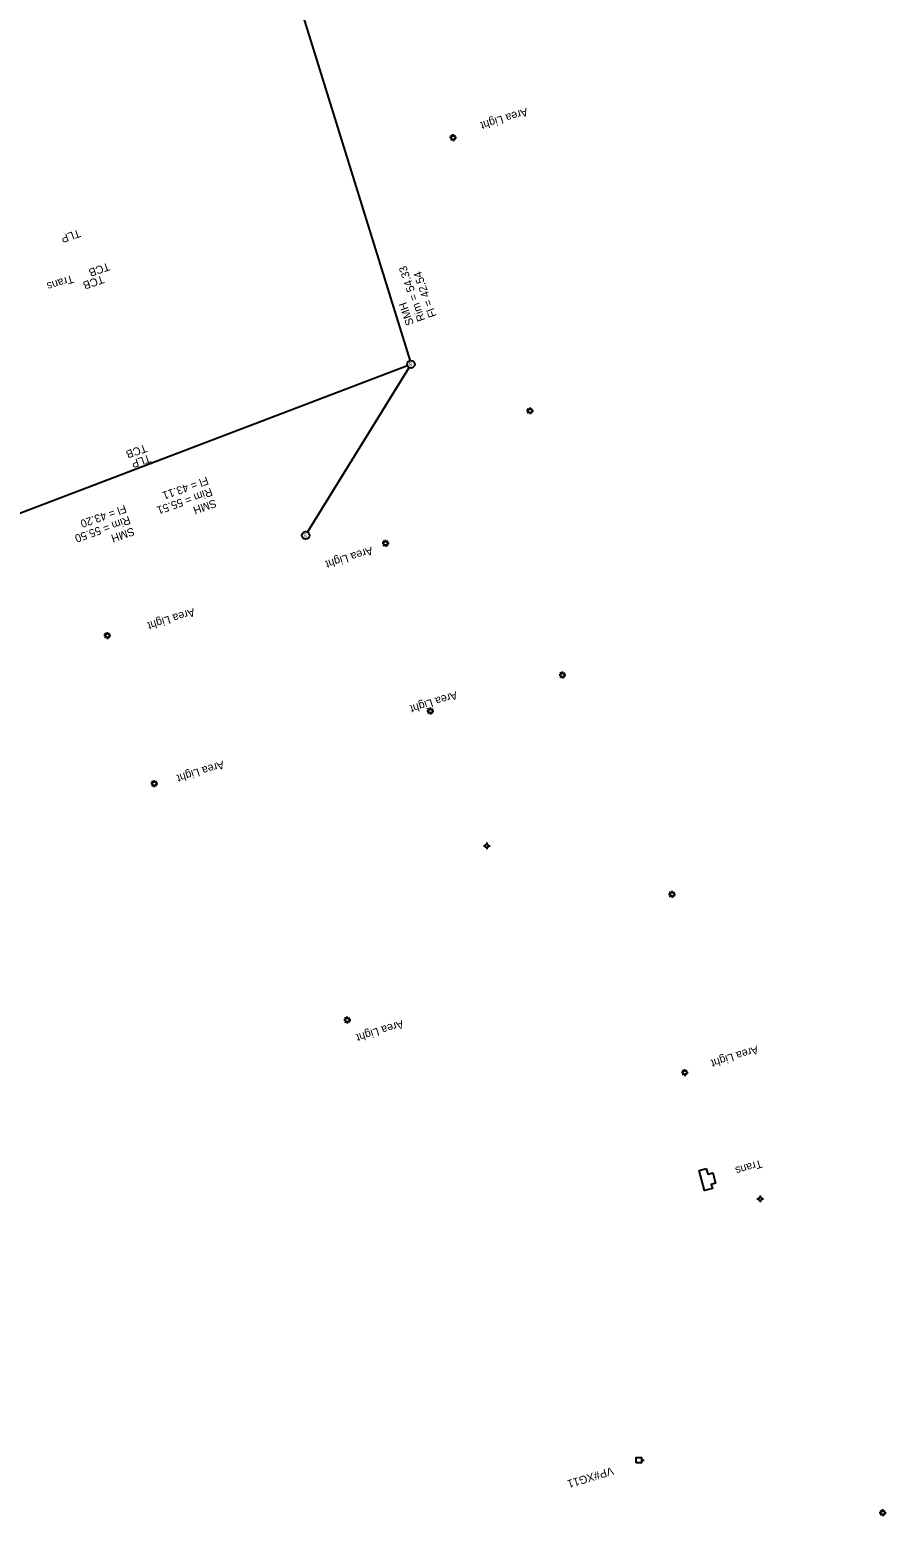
# Model space of a CAD drawing. Extents: x 3872070 to 3879223, y 293944 to 310567.
# Drawn here: x 3875034 to 3875355, y 305445 to 306002 of the extents above; entities that cross this region are included whole.
import ezdxf

# ---------------------------------------------------------------- set-up
doc = ezdxf.new("R2010")
doc.units = 0
for name, color, linetype in [('Level 3', 7, 'Continuous'), ('Level 33', 7, 'Continuous'), ('Level 34', 7, 'Continuous'), ('Level 39', 7, 'Continuous'), ('Level 4', 7, 'Continuous'), ('Level 5', 7, 'Continuous')]:
    doc.layers.add(name, color=color, linetype=linetype)

msp = doc.modelspace()

# ---------------------------------------------------------------- linework, layer by layer
at = {"layer": 'Level 3'}
for p, q in [((3875176.36, 305878.22), (3875111.39, 306087.65)), ((3875174.8, 305876.27), (3875020.61, 305817.48)), ((3875137.72, 305814.13), (3875175.9, 305875.76))]:
    msp.add_line(p, q, dxfattribs=at)
for centre in [(3875176.54, 305876.99), (3875137.08, 305812.87)]:
    msp.add_circle(centre, 1.41, dxfattribs=at)
at = {"layer": 'Level 4'}
for p, q in [((3875191.6, 305961.94), (3875191.03, 305961.94)), ((3875191.81, 305962.45), (3875191.41, 305962.86)), ((3875192.33, 305962.66), (3875192.33, 305963.24)), ((3875192.84, 305962.45), (3875193.25, 305962.86)), ((3875193.05, 305961.94), (3875193.63, 305961.94)), ((3875191.41, 305961.02), (3875191.81, 305961.42)), ((3875192.33, 305961.21), (3875192.33, 305960.64)), ((3875193.25, 305961.02), (3875192.84, 305961.42)), ((3875220.43, 305859.54), (3875219.86, 305859.54)), ((3875220.64, 305860.06), (3875220.24, 305860.46)), ((3875220.24, 305858.62), (3875220.64, 305859.03)), ((3875221.16, 305860.27), (3875221.16, 305860.84)), ((3875221.16, 305858.82), (3875221.16, 305858.24)), ((3875221.67, 305860.06), (3875222.08, 305860.46)), ((3875222.08, 305858.62), (3875221.67, 305859.03)), ((3875221.88, 305859.54), (3875222.46, 305859.54)), ((3875166.28, 305809.89), (3875165.71, 305809.89)), ((3875166.49, 305810.41), (3875166.09, 305810.81)), ((3875166.09, 305808.98), (3875166.49, 305809.38)), ((3875167.01, 305810.62), (3875167.01, 305811.19)), ((3875167.01, 305809.17), (3875167.01, 305808.59)), ((3875167.52, 305810.41), (3875167.93, 305810.81)), ((3875167.93, 305808.98), (3875167.52, 305809.38)), ((3875167.73, 305809.89), (3875168.31, 305809.89)), ((3875062.07, 305775.32), (3875061.5, 305775.32)), ((3875062.29, 305775.84), (3875061.88, 305776.24)), ((3875061.88, 305774.41), (3875062.29, 305774.81)), ((3875062.8, 305776.05), (3875062.8, 305776.62)), ((3875062.8, 305774.6), (3875062.8, 305774.02)), ((3875063.31, 305775.84), (3875063.72, 305776.24)), ((3875063.72, 305774.41), (3875063.31, 305774.81)), ((3875063.52, 305775.32), (3875064.1, 305775.32)), ((3875232.8, 305761.03), (3875232.39, 305761.44)), ((3875233.31, 305761.24), (3875233.31, 305761.82)), ((3875233.82, 305761.03), (3875234.23, 305761.44)), ((3875232.58, 305760.52), (3875232.01, 305760.52)), ((3875232.39, 305759.6), (3875232.8, 305760.01)), ((3875233.31, 305759.79), (3875233.31, 305759.22)), ((3875234.23, 305759.6), (3875233.82, 305760.01)), ((3875234.03, 305760.52), (3875234.61, 305760.52)), ((3875183.1, 305747.03), (3875182.52, 305747.03)), ((3875183.31, 305747.54), (3875182.91, 305747.95)), ((3875182.91, 305746.11), (3875183.31, 305746.52)), ((3875183.83, 305747.75), (3875183.83, 305748.33)), ((3875183.83, 305746.3), (3875183.83, 305745.73)), ((3875184.34, 305747.54), (3875184.74, 305747.95)), ((3875184.74, 305746.11), (3875184.34, 305746.52)), ((3875184.55, 305747.03), (3875185.12, 305747.03)), ((3875079.64, 305719.82), (3875079.06, 305719.82)), ((3875079.85, 305720.34), (3875079.44, 305720.74)), ((3875079.44, 305718.91), (3875079.85, 305719.31)), ((3875080.36, 305720.55), (3875080.36, 305721.12)), ((3875080.36, 305719.1), (3875080.36, 305718.52)), ((3875080.87, 305720.34), (3875081.28, 305720.74)), ((3875081.28, 305718.91), (3875080.87, 305719.31)), ((3875081.09, 305719.82), (3875081.66, 305719.82)), ((3875273.66, 305678.3), (3875273.08, 305678.3)), ((3875273.87, 305678.81), (3875273.46, 305679.22)), ((3875273.46, 305677.38), (3875273.87, 305677.79)), ((3875274.38, 305679.02), (3875274.38, 305679.6)), ((3875274.38, 305677.57), (3875274.38, 305677)), ((3875274.9, 305678.81), (3875275.3, 305679.22)), ((3875275.3, 305677.38), (3875274.9, 305677.79)), ((3875275.11, 305678.3), (3875275.68, 305678.3)), ((3875151.95, 305631.25), (3875151.38, 305631.25)), ((3875152.16, 305631.76), (3875151.76, 305632.17)), ((3875151.76, 305630.33), (3875152.16, 305630.74)), ((3875152.68, 305631.97), (3875152.68, 305632.55)), ((3875152.68, 305630.52), (3875152.68, 305629.95)), ((3875153.19, 305631.76), (3875153.6, 305632.17)), ((3875153.6, 305630.33), (3875153.19, 305630.74)), ((3875153.4, 305631.25), (3875153.98, 305631.25)), ((3875278.43, 305611.54), (3875277.85, 305611.54)), ((3875278.64, 305612.05), (3875278.23, 305612.46)), ((3875278.23, 305610.62), (3875278.64, 305611.03)), ((3875279.15, 305612.27), (3875279.15, 305612.84)), ((3875279.15, 305610.82), (3875279.15, 305610.24)), ((3875279.67, 305612.05), (3875280.07, 305612.46)), ((3875280.07, 305610.62), (3875279.67, 305611.03)), ((3875279.88, 305611.54), (3875280.45, 305611.54)), ((3875262.94, 305466.24), (3875263.94, 305466.24)), ((3875352.6, 305446.53), (3875352.03, 305446.53)), ((3875352.81, 305447.04), (3875352.41, 305447.45)), ((3875352.41, 305445.61), (3875352.81, 305446.02)), ((3875353.33, 305447.26), (3875353.33, 305447.83)), ((3875353.33, 305445.8), (3875353.33, 305445.23)), ((3875353.84, 305447.04), (3875354.25, 305447.45)), ((3875354.25, 305445.61), (3875353.84, 305446.02)), ((3875354.05, 305446.53), (3875354.63, 305446.53))]:
    msp.add_line(p, q, dxfattribs=at)
msp.add_lwpolyline([(3875287.2, 305575.53), (3875287.76, 305573.45), (3875289.6, 305573.94), (3875290.64, 305570.03), (3875289.08, 305569.61), (3875289.49, 305568.11), (3875286.52, 305567.32), (3875284.52, 305574.81), (3875287.2, 305575.53)], dxfattribs=at)
msp.add_lwpolyline([(3875260.94, 305465.24), (3875260.94, 305467.24), (3875262.94, 305467.24), (3875262.94, 305465.24)], close=True, dxfattribs=at)
for centre in [(3875192.33, 305961.94), (3875221.16, 305859.54), (3875167.01, 305809.89), (3875062.8, 305775.32), (3875233.31, 305760.52), (3875183.83, 305747.03), (3875080.36, 305719.82), (3875274.38, 305678.3), (3875152.68, 305631.25), (3875279.15, 305611.54), (3875353.33, 305446.53)]:
    msp.add_circle(centre, 0.725, dxfattribs=at)
at = {"layer": 'Level 5'}
for p, q in [((3875203.68, 305696.46), (3875204.3, 305696.46)), ((3875204.93, 305697.71), (3875204.93, 305697.08)), ((3875204.93, 305695.84), (3875204.93, 305695.21)), ((3875205.54, 305696.46), (3875206.18, 305696.46)), ((3875306.19, 305564.16), (3875306.81, 305564.16)), ((3875307.44, 305565.41), (3875307.44, 305564.78)), ((3875307.44, 305563.54), (3875307.44, 305562.91)), ((3875308.06, 305564.16), (3875308.69, 305564.16))]:
    msp.add_line(p, q, dxfattribs=at)
for centre in [(3875204.93, 305696.46), (3875307.44, 305564.16)]:
    msp.add_circle(centre, 0.625, dxfattribs=at)

# ---------------------------------------------------------------- texts
at = {"layer": 'Level 3'}
for p in [(3875177.01, 305877.7), (3875137.56, 305813.58)]:
    msp.add_text('S', height=1.41, rotation=180, dxfattribs=at).set_placement(p)
at = {"layer": 'Level 33'}
for s, rotation, p in [('Rim = 54.33', 109.4366, (3875181.94, 305893.65)), ('Fl = 42.54', 109.4366, (3875186.18, 305895.14)), ('SMH', 109.4366, (3875177.69, 305892.15)), ('Fl = 43.11', 199.4366, (3875100.02, 305834.95)), ('Rim = 55.51', 199.4366, (3875101.52, 305830.71)), ('Fl = 43.20', 199.4366, (3875069.29, 305824.4)), ('SMH', 199.4366, (3875103.02, 305826.47)), ('Rim = 55.50', 199.4366, (3875070.79, 305820.16)), ('SMH', 199.4366, (3875072.29, 305815.91))]:
    msp.add_text(s, height=3, rotation=rotation, dxfattribs=at).set_placement(p)
at = {"layer": 'Level 34'}
for s, rotation, p in [('Area Light', 197.2497, (3875219.78, 305973.12)), ('Trans', 197.4877, (3875049.59, 305910.51)), ('Area Light', 197.2497, (3875161.71, 305808.66)), ('Area Light', 197.2497, (3875095.01, 305785.64)), ('Area Light', 197.2497, (3875193.39, 305754.47)), ('Area Light', 197.2497, (3875106.01, 305728.45)), ('Area Light', 197.2497, (3875173.23, 305631.24)), ('Area Light', 197.2497, (3875306.15, 305621.65)), ('Trans', 196.5167, (3875307.63, 305578.9)), ('VP#XG11', 196.9281, (3875251.92, 305463.8))]:
    msp.add_text(s, height=3, rotation=rotation, dxfattribs=at).set_placement(p)
at = {"layer": 'Level 39'}
for s, p in [('TLP', (3875052.04, 305927.65)), ('TCB', (3875063.05, 305915.19)), ('TCB', (3875060.89, 305910.39)), ('TCB', (3875076.97, 305847.08)), ('TLP', (3875078.41, 305843.24))]:
    msp.add_text(s, height=3, rotation=199.1512, dxfattribs=at).set_placement(p)

doc.saveas('drawing.dxf')
